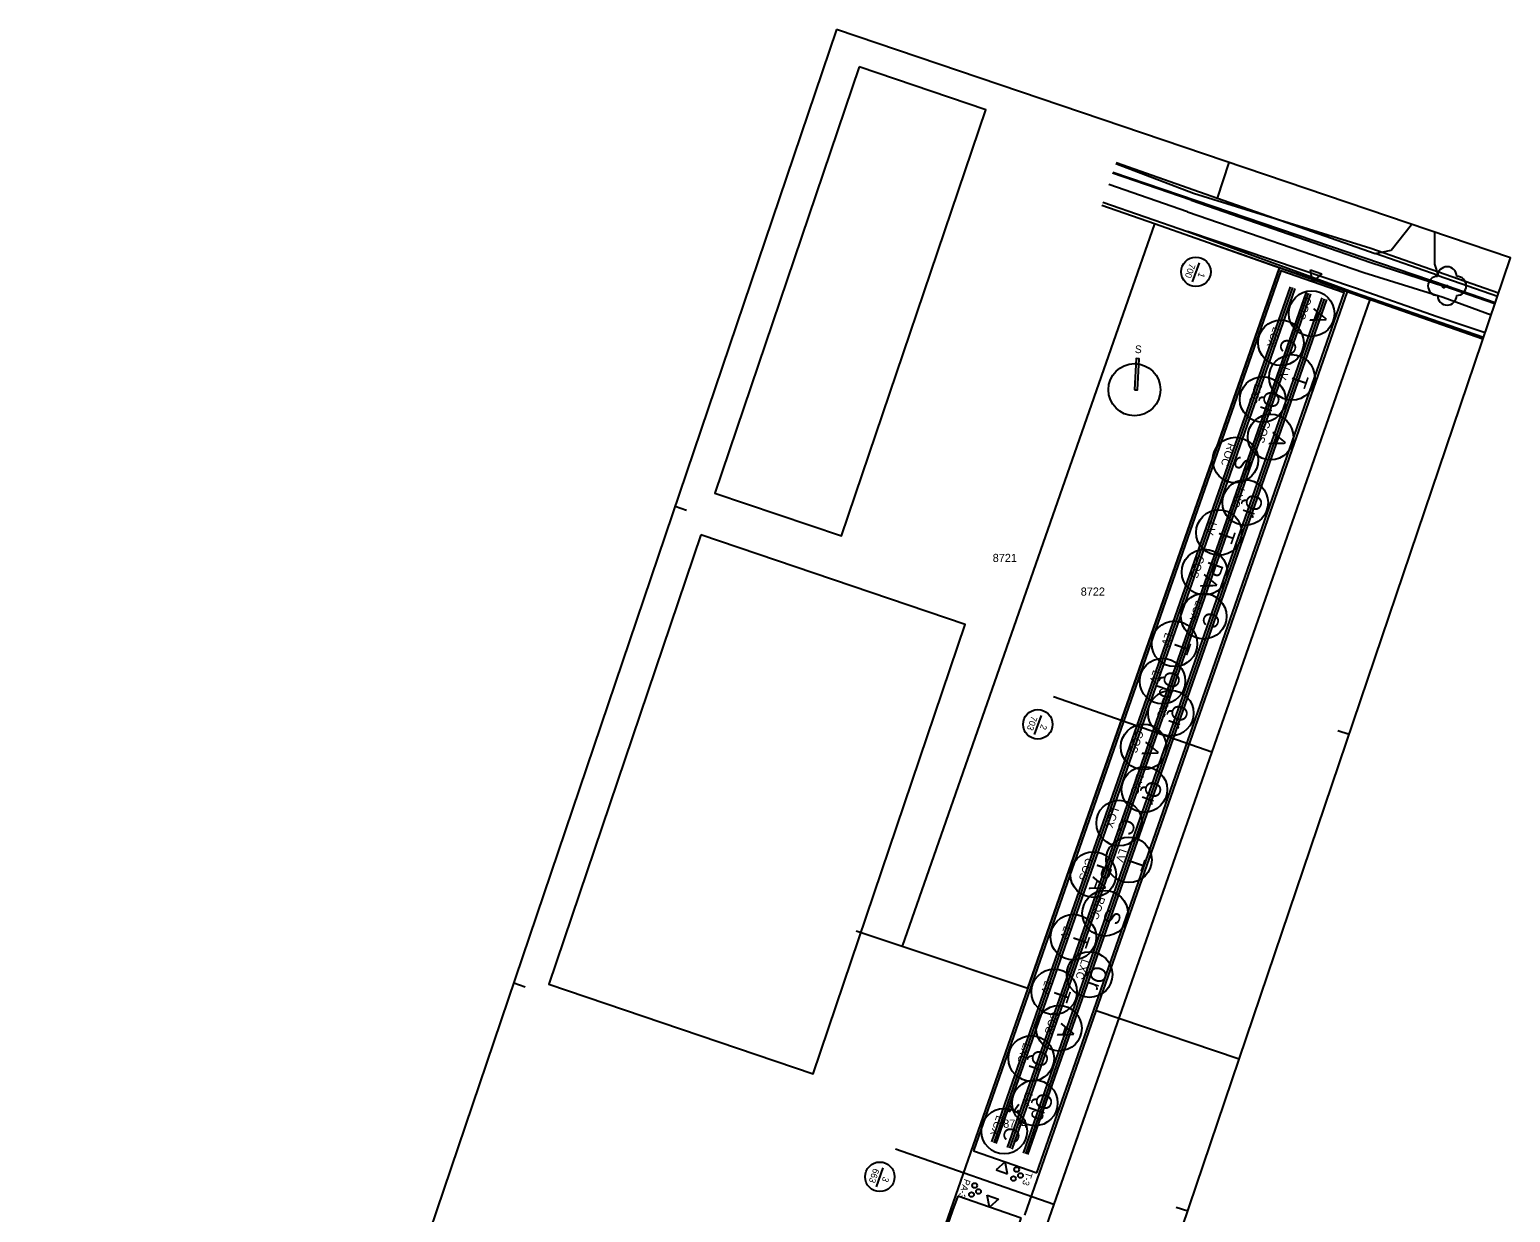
# Model space of a CAD drawing. Extents: x -639224 to -638915, y -1200697 to -1200152.
# Drawn here: x -639224.2 to -638915.2, y -1200398.7 to -1200151.9 of the extents above; entities that cross this region are included whole.
import ezdxf

# ---------------------------------------------------------------- set-up
doc = ezdxf.new("R2010")
doc.units = 0
for name, color, linetype in [('Obvody jako plochy', 7, 'Continuous'), ('plot', 7, 'Continuous'), ('stromy', 7, 'Continuous'), ('trojrady', 7, 'Continuous'), ('tráva', 7, 'Continuous'), ('Vrstva 18', 7, 'Continuous'), ('Vrstva 23', 7, 'Continuous'), ('Vrstva 25', 7, 'Continuous'), ('Vrstva 40', 7, 'Continuous'), ('Vrstva 44', 7, 'Continuous'), ('Vrstva 63', 7, 'Continuous'), ('značky', 7, 'Continuous'), ('ŘEŠENÉ', 7, 'Continuous')]:
    doc.layers.add(name, color=color, linetype=linetype)

msp = doc.modelspace()

# ---------------------------------------------------------------- linework, layer by layer
at = {"layer": 'Obvody jako plochy'}
for p, q in [((-638997.46, -1200179.63), (-638976.31, -1200187.05)), ((-638976.31, -1200187.05), (-638973.88, -1200179.65)), ((-638976.31, -1200187.05), (-638943.42, -1200198.59)), ((-638989.47, -1200192.42), (-639000.48, -1200188.56)), ((-638989.47, -1200192.42), (-639042.11, -1200343.15)), ((-638963.38, -1200201.56), (-638989.47, -1200192.42)), ((-638940.08, -1200197.92), (-638935.85, -1200192.53)), ((-638930.99, -1200194.17), (-638931.06, -1200194.38)), ((-638931.06, -1200194.38), (-638931.06, -1200200.86)), ((-638943.42, -1200198.59), (-638940.08, -1200197.92)), ((-638930.23, -1200203.2), (-638943.42, -1200198.59)), ((-639015.91, -1200351.87), (-638963.38, -1200201.56)), ((-638949.21, -1200206.52), (-638963.38, -1200201.56)), ((-638931.06, -1200200.86), (-638930.23, -1200203.2)), ((-638930.23, -1200203.2), (-638917.9, -1200207.53)), ((-639001.65, -1200356.62), (-638949.21, -1200206.52)), ((-638949.21, -1200206.52), (-638920.91, -1200216.41)), ((-639051.74, -1200339.95), (-639042.11, -1200343.15)), ((-639042.11, -1200343.15), (-639015.91, -1200351.87)), ((-639015.91, -1200351.87), (-639032.07, -1200398.12)), ((-639016.55, -1200399.26), (-639001.65, -1200356.62)), ((-638971.81, -1200366.73), (-639001.65, -1200356.62)), ((-639032.07, -1200398.12), (-639091.42, -1200567.98))]:
    msp.add_line(p, q, dxfattribs=at)
at = {"layer": 'plot'}
for p, q in [((-638956.93, -1200202.02), (-638954.53, -1200202.86)), ((-638956.46, -1200204.51), (-638956.93, -1200202.02)), ((-638954.53, -1200202.86), (-638956.46, -1200204.51)), ((-639027.24, -1200385.82), (-639014, -1200390.44)), ((-639020.62, -1200388.13), (-639022.54, -1200389.79)), ((-639020.15, -1200390.62), (-639020.62, -1200388.13)), ((-639022.54, -1200389.79), (-639020.15, -1200390.62)), ((-639017.3, -1200399.88), (-639030.54, -1200395.26)), ((-639024.39, -1200395.07), (-639021.99, -1200395.92)), ((-639023.92, -1200397.57), (-639024.39, -1200395.07)), ((-639021.99, -1200395.92), (-639023.92, -1200397.57))]:
    msp.add_line(p, q, dxfattribs=at)
for points in [[(-639014, -1200390.44), (-639002.12, -1200356.46), (-638949.85, -1200206.83), (-638963.07, -1200202.2), (-639015.44, -1200352.03), (-639027.24, -1200385.82)], [(-639030.54, -1200395.26), (-639031.6, -1200398.28), (-639090.78, -1200567.66), (-639077.45, -1200572.02), (-639076.62, -1200569.65), (-639017.3, -1200399.88)]]:
    msp.add_lwpolyline(points, dxfattribs=at)
at = {"layer": 'stromy'}
for centre in [(-638956.68, -1200211.13), (-638963.08, -1200217.22), (-638960.79, -1200224.45), (-638966.89, -1200229.05), (-638965.23, -1200236.89), (-638972.59, -1200241.7), (-638970.52, -1200250.58), (-638976.01, -1200256.83), (-638979.02, -1200265.08), (-638979.2, -1200274.3), (-638985.29, -1200280.02), (-638987.79, -1200287.82), (-638986.05, -1200294.51), (-638991.74, -1200301.55), (-638991.57, -1200310.44), (-638996.83, -1200317.44), (-638994.81, -1200325.11), (-639002.24, -1200328.18), (-638999.79, -1200336.26), (-639006.4, -1200341.24), (-639003.02, -1200349.06), (-639010.4, -1200352.65), (-639009.4, -1200360.25), (-639015.19, -1200366.54), (-639014.44, -1200375.84), (-639020.83, -1200381.72)]:
    msp.add_circle(centre, 4.76, dxfattribs=at)
at = {"layer": 'trojrady'}
for points in [[(-639051.09, -1200159.68), (-639081.19, -1200248.59), (-639054.79, -1200257.53), (-639024.68, -1200168.62)], [(-639084.16, -1200257.33), (-639115.89, -1200351.06), (-639060.69, -1200369.75), (-639028.95, -1200276.03)]]:
    msp.add_lwpolyline(points, close=True, dxfattribs=at)
for points in [[(-639023.42, -1200383.97), (-639012.6, -1200353.01), (-638961.07, -1200205.55)], [(-639022.95, -1200384.14), (-639012.13, -1200353.17), (-638960.59, -1200205.71)], [(-639022.48, -1200384.3), (-639011.66, -1200353.34), (-638960.12, -1200205.88)], [(-639020.12, -1200385.13), (-639009.3, -1200354.16), (-638957.76, -1200206.7)], [(-639019.64, -1200385.29), (-639008.82, -1200354.33), (-638957.29, -1200206.87)], [(-639019.17, -1200385.46), (-639008.35, -1200354.49), (-638956.82, -1200207.04)], [(-639016.81, -1200386.28), (-639005.99, -1200355.32), (-638954.46, -1200207.86)], [(-639016.34, -1200386.45), (-639005.52, -1200355.48), (-638953.99, -1200208.03)], [(-639015.87, -1200386.61), (-639005.05, -1200355.65), (-638953.52, -1200208.19)]]:
    msp.add_lwpolyline(points, dxfattribs=at)
for centre in [(-639018.9, -1200391.61), (-639018.23, -1200389.71), (-639017.43, -1200390.97), (-639027.66, -1200394.95), (-639026.99, -1200393.05), (-639026.19, -1200394.31)]:
    msp.add_circle(centre, 0.5, dxfattribs=at)
at = {"layer": 'tráva'}
for p, q in [((-638963.38, -1200201.56), (-639015.91, -1200351.87)), ((-638949.21, -1200206.52), (-638963.38, -1200201.56)), ((-639001.65, -1200356.62), (-638949.21, -1200206.52)), ((-639015.91, -1200351.87), (-639032.07, -1200398.12)), ((-639016.55, -1200399.26), (-639001.65, -1200356.62)), ((-639032.07, -1200398.12), (-639091.42, -1200567.98))]:
    msp.add_line(p, q, dxfattribs=at)
at = {"layer": 'Vrstva 23'}
msp.add_circle((-638929.08, -1200205.44), 0.3, dxfattribs=at)
at = {"layer": 'Vrstva 25'}
msp.add_lwpolyline([(-639017.8, -1200376.14), (-639018.8, -1200377.64), (-639019.8, -1200376.14)], dxfattribs=at)
for centre in [(-639019.7, -1200377.54), (-639017.9, -1200377.54)]:
    msp.add_circle(centre, 0.1, dxfattribs=at)
at = {"layer": 'Vrstva 40'}
for p, q in [((-638998.13, -1200181.61), (-638928.4, -1200205.37)), ((-638928.4, -1200205.37), (-638928.4, -1200205.37)), ((-638928.4, -1200205.37), (-638918.35, -1200208.86))]:
    msp.add_line(p, q, dxfattribs=at)
msp.add_circle((-638928.4, -1200205.37), 0.1, dxfattribs=at)
for centre, start, end in [((-638928.4, -1200203.37), 0, 180), ((-638930.4, -1200205.37), 90, 270), ((-638926.4, -1200205.37), 270, 90), ((-638928.4, -1200207.37), 180, 0)]:
    msp.add_arc(centre, 2, start, end, dxfattribs=at)
at = {"layer": 'Vrstva 44'}
for p, q in [((-638997.52, -1200179.81), (-638981.32, -1200186.03)), ((-638982.56, -1200189.89), (-638999.01, -1200184.21)), ((-638981.79, -1200187.45), (-638998.21, -1200181.84)), ((-639000.26, -1200187.9), (-638982.61, -1200194.01)), ((-638981.79, -1200187.45), (-638944.34, -1200200.51)), ((-638981.32, -1200186.03), (-638944.31, -1200197.5)), ((-638982.56, -1200189.89), (-638945.76, -1200202.6)), ((-638947.55, -1200205.84), (-638982.61, -1200194.01)), ((-638982.61, -1200194.01), (-638947.91, -1200206.66)), ((-638944.31, -1200197.5), (-638917.66, -1200206.81)), ((-638945.76, -1200202.6), (-638929.22, -1200207.68)), ((-638944.34, -1200200.51), (-638929.08, -1200205.44)), ((-638930.48, -1200211.84), (-638947.55, -1200205.84)), ((-638918.44, -1200209.11), (-638929.08, -1200205.44)), ((-638947.91, -1200206.66), (-638920.78, -1200216.03)), ((-638929.22, -1200207.68), (-638919.22, -1200211.41)), ((-638920.48, -1200215.13), (-638930.48, -1200211.84))]:
    msp.add_line(p, q, dxfattribs=at)
at = {"layer": 'Vrstva 63'}
for p, q in [((-639089.52, -1200251.35), (-639087.15, -1200252.15)), ((-638948.87, -1200298.98), (-638951.23, -1200298.17)), ((-639123.2, -1200350.8), (-639120.83, -1200351.6)), ((-639123.2, -1200350.8), (-639120.83, -1200351.6)), ((-638982.54, -1200398.43), (-638984.91, -1200397.63)), ((-638982.54, -1200398.43), (-638984.91, -1200397.63))]:
    msp.add_line(p, q, dxfattribs=at)
for points in [[(-639055.85, -1200151.89), (-639224.22, -1200649.16), (-639083.57, -1200696.79), (-638915.19, -1200199.52)], [(-638993.65, -1200227.02), (-638993.03, -1200227.05), (-638992.69, -1200220.56), (-638993.31, -1200220.53)]]:
    msp.add_lwpolyline(points, close=True, dxfattribs=at)
msp.add_circle((-638993.65, -1200227.02), 5.44, dxfattribs=at)
at = {"layer": 'značky'}
for p, q in [((-638977.53, -1200196.62), (-638944.49, -1200208.17)), ((-638980.16, -1200200.56), (-638981.58, -1200204.55)), ((-639010.52, -1200291.03), (-638977.48, -1200302.57)), ((-639013.14, -1200294.97), (-639014.56, -1200298.95)), ((-639043.5, -1200385.43), (-639010.46, -1200396.98)), ((-639046.13, -1200389.37), (-639047.55, -1200393.36))]:
    msp.add_line(p, q, dxfattribs=at)
msp.add_lwpolyline([(-638944.49, -1200208.17), (-639071.39, -1200571.37), (-639072.81, -1200576.05)], dxfattribs=at)
for centre in [(-638980.82, -1200202.43), (-639013.81, -1200296.84), (-639046.79, -1200391.24)]:
    msp.add_circle(centre, 3.08, dxfattribs=at)
at = {"layer": 'ŘEŠENÉ'}
for p, q in [((-638963.38, -1200201.56), (-639015.91, -1200351.87)), ((-638949.21, -1200206.52), (-638963.38, -1200201.56)), ((-639001.65, -1200356.62), (-638949.21, -1200206.52)), ((-639015.91, -1200351.87), (-639032.07, -1200398.12)), ((-639016.55, -1200399.26), (-639001.65, -1200356.62)), ((-639032.07, -1200398.12), (-639091.42, -1200567.98))]:
    msp.add_line(p, q, dxfattribs=at)

# ---------------------------------------------------------------- texts
at = {"layer": 'plot'}
for s, p in [('PA-3', (-639029.12, -1200391.57)), ('T-3', (-639016.19, -1200390.13))]:
    msp.add_text(s, height=1.4, rotation=250.7402, dxfattribs=at).set_placement(p)
at = {"layer": 'stromy'}
for s, height, p in [('COS', 1.651, (-638958.17, -1200207.52)), ('A', 3.3, (-638956.19, -1200209.91)), ('LCX', 1.651, (-638964.64, -1200213.8)), ('C', 3.3, (-638962.59, -1200215.98)), ('LV', 1.651, (-638962.69, -1200222.02)), ('T', 3.3, (-638960.34, -1200223.36)), ('LXC', 1.651, (-638968.46, -1200225.67)), ('Qr', 3.302, (-638966.07, -1200226.9)), ('COS', 1.651, (-638966.72, -1200233.29)), ('A', 3.3, (-638964.74, -1200235.68)), ('ROC', 1.651, (-638974.06, -1200238.01)), ('S', 3.3, (-638972.13, -1200240.56)), ('LXC', 1.651, (-638972.09, -1200247.19)), ('Qr', 3.302, (-638969.71, -1200248.42)), ('LV', 1.651, (-638977.92, -1200254.39)), ('T', 3.3, (-638975.57, -1200255.74)), ('COS', 1.651, (-638980.52, -1200261.47)), ('PA', 3.302, (-638978.09, -1200262.58)), ('LCX', 1.651, (-638980.76, -1200270.88)), ('C', 3.3, (-638978.7, -1200273.05)), ('LV', 1.651, (-638987.19, -1200277.59)), ('T', 3.3, (-638984.85, -1200278.93)), ('LV', 1.651, (-638989.69, -1200285.39)), ('Qp', 3.302, (-638986.88, -1200285.38)), ('LXC', 1.651, (-638987.63, -1200291.13)), ('Qr', 3.302, (-638985.24, -1200292.35)), ('COS', 1.651, (-638993.23, -1200297.94)), ('A', 3.3, (-638991.25, -1200300.33)), ('LXC', 1.651, (-638993.14, -1200307.05)), ('Qr', 3.302, (-638990.76, -1200308.28)), ('LCX', 1.651, (-638998.39, -1200314.02)), ('C', 3.3, (-638996.33, -1200316.2)), ('LV', 1.651, (-638996.71, -1200322.67)), ('COS', 1.651, (-639003.73, -1200324.57)), ('PA', 3.302, (-639001.31, -1200325.68)), ('T', 3.3, (-638994.37, -1200324.02)), ('ROC', 1.651, (-639001.26, -1200332.57)), ('S', 3.3, (-638999.34, -1200335.12)), ('LV', 1.651, (-639008.3, -1200338.8)), ('T', 3.3, (-639005.95, -1200340.14)), ('LXC', 1.651, (-639004.59, -1200345.68)), ('Qr', 3.302, (-639002.21, -1200346.9)), ('LV', 1.651, (-639012.31, -1200350.21)), ('T', 3.3, (-639009.96, -1200351.55)), ('COS', 1.651, (-639010.89, -1200356.64)), ('A', 3.3, (-639008.91, -1200359.03)), ('LXC', 1.651, (-639016.76, -1200363.15)), ('Qr', 3.302, (-639014.38, -1200364.38)), ('LV', 1.651, (-639016.34, -1200373.41)), ('Qp', 3.302, (-639013.53, -1200373.4)), ('LCX', 1.651, (-639022.39, -1200378.3)), ('C', 3.3, (-639020.33, -1200380.48))]:
    msp.add_text(s, height=height, rotation=250.8987, dxfattribs=at).set_placement(p)
at = {"layer": 'Vrstva 18'}
for s, p in [('8721', (-639023.23, -1200262.97)), ('8722', (-639004.86, -1200269.99)), ('8724', (-639021.04, -1200381.01))]:
    msp.add_text(s, height=1.7, dxfattribs=at).set_placement(p)
at = {"layer": 'Vrstva 63'}
msp.add_text('S', height=1.6, rotation=356.9882, dxfattribs=at).set_placement((-638993.59, -1200219.35))
at = {"layer": 'značky'}
for s, height, p in [('700', 1.355, (-638982.14, -1200200.58)), ('1', 1.35, (-638980.14, -1200202.44)), ('703', 1.355, (-639015.12, -1200294.98)), ('2', 1.35, (-639013.08, -1200296.73)), ('663', 1.355, (-639048.11, -1200389.38)), ('3', 1.35, (-639046.06, -1200391.12))]:
    msp.add_text(s, height=height, rotation=250.3836, dxfattribs=at).set_placement(p)

doc.saveas('drawing.dxf')
